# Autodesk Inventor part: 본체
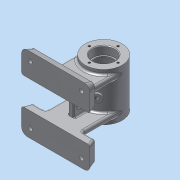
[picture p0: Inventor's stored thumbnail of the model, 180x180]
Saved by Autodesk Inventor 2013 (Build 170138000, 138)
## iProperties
Created: 2016-07
Part Number: 본체
Material: 알루미늄 6061
Document SubType Name: Modeling
Designer: dgall
Density: 1 g/cm^3
Author: dgall
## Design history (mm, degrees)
sketch "스케치1"
  geometry: C1 r 27 at (0, 0); 1 further point
  constraints: 1 centre point, 1 coincident
  dimensions: "d0" = 54 diameter of C1
extrude "돌출1" new body sketch "스케치1" distance "d2" = 70; taper "d3" = 0 deg
node "작업 평면1"
sketch "스케치2"
  geometry: L1 (27, 70)-(-27, 70) reference; L2 (-27, 0)-(27, 0) reference; L3 (50, 90)-(-50, 90); L4 (-50, 90)-(-50, -20); L5 (-50, -20)-(50, -20); L6 (50, -20)-(50, 90); L7 (27, 0)-(27, 70) reference; L8 (-27, 0)-(-27, 70) reference; 5 further points
  constraints: 8 end point, 4 midpoint, 2 parallel, 1 horizontal, 1 horizontal alignment, 1 perpendicular, 1 vertical alignment
  dimensions: "d5" = 100 distance between parallel lines of L4 L6; "d7" = 110 distance between parallel lines of L3 L5
extrude "돌출2" join sketch "스케치2" distance "d8" = 12; taper "d9" = -20 deg
sketch "스케치3"
  geometry: L1 (-70, 55)-(-58, 55); L2 (-58, 55)-(-58, 15); L3 (-58, 15)-(-70, 15); L4 (-70, 15)-(-70, 55); L5 (-58, -15.632)-(-58, 85.632) reference; L6 (-70, 90)-(-70, -20) reference; 6 further points
  constraints: 8 end point, 5 midpoint, 3 coincident, 2 parallel, 1 horizontal, 1 perpendicular
  dimensions: "d10" = 40 distance of L3.end L1.start
extrude "돌출3" cut sketch "스케치3" stored distance "d12" = 12; taper "d13" = 0 deg
sketch "스케치4"
  geometry: L1 (4.368, 12)-(95.632, 12) reference; L2 (23, 70)-(23, 12); L3 (77, 12)-(77, 70); A1 r 27 centre (50, 70) between (23, 70) and (77, 70) reference; 1 further point
  constraints: 4 end point, 2 perpendicular, 2 point on circle, 2 point on line, 1 parallel
  dimensions: "d14" = 54 distance between parallel lines of L3 L2
extrude "돌출4" join sketch "스케치4" distance "d15" = 8; taper "d16" = 0 deg
sketch "스케치5"
  geometry: L1 (4.368, 12)-(95.632, 12) reference; L2 (23, 70)-(23, 12); L3 (77, 12)-(77, 70); A1 r 27 centre (50, 70) between (23, 70) and (77, 70) reference; 1 further point
  constraints: 4 end point, 2 parallel, 2 point on circle, 2 point on line, 1 perpendicular
  dimensions: "d17" = 54 distance between parallel lines of L3 L2
extrude "돌출5" join sketch "스케치5" distance "d18" = 8; taper "d19" = 0 deg
sketch "스케치6"
  geometry: L1 (0, 55)-(-58, 55) reference; L2 (-58, 15)-(0, 15) reference; L3 (-48, 55)-(-22, 55); L4 (-22, 55)-(-22, 15); L5 (-22, 15)-(-48, 15); L6 (-48, 15)-(-48, 55); L7 (-34.5, 43)-(-34.5, 27); L8 (-41.5, 27)-(-41.5, 43); L9 (-70, 15)-(-70, -20) reference; L10 (-27, 0)-(-27, 70) reference; A1 r 3.5 centre (-38, 27) between (-41.5, 27) and (-34.5, 27); A2 r 3.5 centre (-38, 43) between (-34.5, 43) and (-41.5, 43); 3 further points
  constraints: 12 end point, 4 parallel, 4 point on circle, 4 tangent, 2 centre point, 2 midpoint, 2 point on line, 1 horizontal, 1 horizontal alignment, 1 perpendicular
  dimensions: "d20" = 3.5 radius of A1; "d22" = 32 distance from line of L9 A1.centre; "d23" = 23 dimension on A2 A1; "d24" = 21 distance between parallel lines of L6 L10; "d25" = 5 distance between parallel lines of L10 L4
extrude "돌출6" join sketch "스케치6" stored distance "d26" = 8; taper "d27" = 0 deg
node "작업 평면2"
sketch "스케치7"
  geometry: L1 (-27, 0)-(-27, 70) reference; L2 (27, 0)-(27, 70) reference; L3 (27, 70)-(-27, 70) reference; L4 (-27, 0)-(27, 0) reference; C1 r 5 at (0, 22); 2 further points
  constraints: 1 centre point, 1 midpoint, 1 vertical alignment
  dimensions: "d28" = 22 distance of point (0, 0) C1.centre; "d29" = 10 diameter of C1
extrude "돌출7" join sketch "스케치7" distance "d30" = 3; taper "d32" = 0 deg; dims "d31" = 1.5, "d33" = 0
node "작업 평면3"
sketch "스케치9"
  geometry: C1 r 27 at (0, 0) reference; C2 r 16 at (0, 0)
  constraints: 1 centre point, 1 coincident
  dimensions: "d40" = 32 diameter of C2
extrude "돌출8" cut sketch "스케치9" distance "d42" = 12; taper "d43" = 0 deg
sketch "스케치10"
  geometry: C1 r 16 at (0, 0) reference; C2 r 14 at (0, 0)
  constraints: 1 centre point, 1 coincident
  dimensions: "d44" = 28 diameter of C2
extrude "돌출9" cut sketch "스케치10" stored distance "d46" = 12; taper "d47" = 0 deg
sketch "스케치11"
  geometry: C1 r 21 at (0, 0); 1 further point
  constraints: 1 centre point, 1 coincident
  dimensions: "d48" = 42 diameter of C1
extrude "돌출10" cut sketch "스케치11" stored distance "d50" = 42; taper "d51" = 0 deg
chamfer "모따기1" distance "d52" = 1; stored, may be unused: second distance "d53" = 2, angle "d54" = 45 deg
fillet "모깎기1" dims "d55" = 0.3
fillet "모깎기2" dims "d56" = 3
fillet "모깎기3" dims "d57" = 2
fillet "모깎기4" dims "d58" = 10, "d59" = 5
fillet "모깎기5" dims "d60" = 10, "d61" = 5
fillet "모깎기6" dims "d62" = 10, "d63" = 5
fillet "모깎기7" dims "d64" = 10, "d65" = 5
fillet "모깎기8" dims "d66" = 3
hole "구멍1" diameter "d69" = 5.188; stored, may be unused: countersink angle "d73" = 90 deg, drill point angle "d75" = 118 deg; dims "d67" = 10, "d68" = 10, "d70" = 10, "d71" = 4, "d72" = 2, "d74" = 8
sketch "스케치12"
  geometry: L1 (30, -12)-(30, -10) reference; L2 (43.532, -12)-(30, -12) reference; L3 (43.532, 11.433)-(43.532, -12) reference; L4 (-41.433, 13.532)-(41.433, 13.532) reference; L5 (-43.532, -12)-(-43.532, 11.433) reference; L6 (-30, -12)-(-43.532, -12) reference; L7 (-30, -10)-(-30, -12) reference; L8 (24, -4)-(-24, -4) reference; L9 (-41.555, -90)-(41.555, -90) reference; L10 (-50, -55)-(-50, -81.555) reference; A1 r 6 centre (24, -10) between (30, -10) and (24, -4) reference; A2 r 6 centre (-24, -10) between (-24, -4) and (-30, -10) reference; 5 further points
  constraints: 2 horizontal alignment, 2 vertical alignment, 2 other
  dimensions: "d85" = 75 distance of point (37.5, -77.5) point (-37.5, -77.5); "d87" = 85 distance of point (-37.5, -77.5) point (-37.5, 7.5); "d88" = 12.5 distance from line of L9 point (-37.5, -77.5); "d89" = 12.5 distance from line of L10 point (-37.5, -77.5)
hole "구멍3" sketch "스케치12" at (-37.5, -77.5), (-37.5, 7.5), (37.5, 7.5), (37.5, -77.5) diameter "d90" = 6; stored, may be unused: countersink angle "d94" = 90 deg, drill point angle "d96" = 118 deg; dims "d91" = 10, "d92" = 10, "d93" = 4, "d95" = 8
sketch "스케치13"
  geometry: C1 r 27 at (0, 0) reference; 1 further point
  constraints: 1 vertical alignment
  dimensions: "d97" = 21 distance of C1.centre point (0, 21)
hole "구멍4" sketch "스케치13" at (0, 21) diameter "d98" = 3.242; stored, may be unused: countersink angle "d102" = 90 deg, drill point angle "d104" = 118 deg; dims "d99" = 8, "d100" = 10, "d101" = 4, "d103" = 10
fillet "모깎기9" dims "d108" = 2
node "작업 평면4"
sketch "스케치14"
  geometry: L1 (-27, 0)-(-27, 70) reference; 2 further points
  constraints: 1 other
  dimensions: "d109" = 35 distance of point (0, 35) point (0, 0); "d110" = 27 distance from line of point (0, 35) L1
feature "엠보싱1" sketch "스케치14" dims "d0" = 54, "d111" = 0.5, "d112" = 0
node "작업 평면5"
sketch "스케치15"
  geometry: L1 (0, 0)-(-15.898, -25.441); L2 (-15.898, -25.441)-(-10.809, -28.621); L3 (-10.809, -28.621)-(-8.862, -25.504); L4 (-15.898, -25.441)-(-14.308, -22.897); A1 r 27 centre (0, 0) between (-21.6, -16.2) and (-5.586, -26.416) reference; 1 further point
  constraints: 8 end point, 3 point on circle, 1 parallel, 1 perpendicular, 1 point on line, 1 vertical alignment
  dimensions: "d116" = 32 deg dimension on L1.start L1.end point (0, -27); "d117" = 12 diameter of L3 L1; "d119" = 30 distance from line of L1.start L2
revolve "회전2" sketch "스케치15" stored, may be unused: angle "d120" = 90 deg
hole "구멍5" diameter "d123" = 5.188; stored, may be unused: countersink angle "d127" = 90 deg, drill point angle "d129" = 118 deg; dims "d121" = 10, "d122" = 10, "d124" = 30, "d125" = 4, "d126" = 2, "d128" = 8
node "솔리드1"
mirror "대칭1"
pattern_circular "원형 패턴1" dims angle "d106" = 360 deg
mirror "대칭2"
node "투영된 루프1"
node "투영된 루프2"
node "투영된 루프3"
other parameters: "d34" = -35, "d114" = -35
